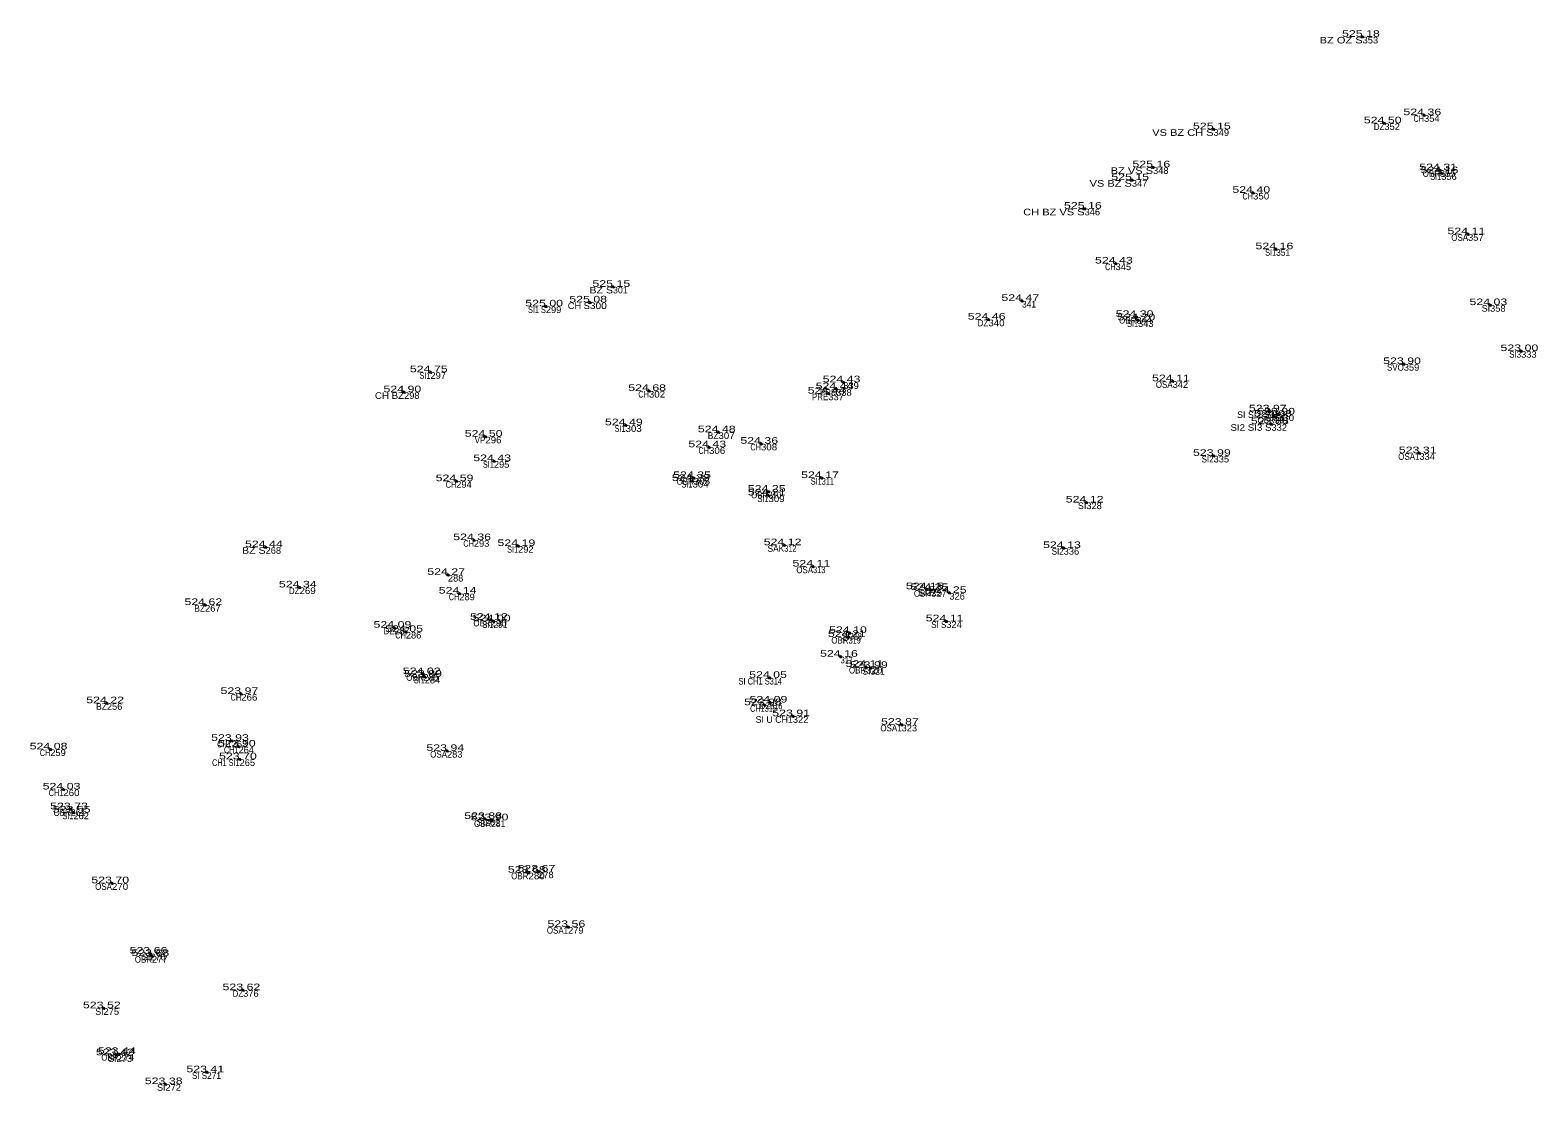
# Model space of a CAD drawing. Extents: x -643086 to -639283, y -1131805 to -1123269.
# Drawn here: x -641196.8 to -641128.3, y -1126069.6 to -1126021.4 of the extents above; entities that cross this region are included whole.
import ezdxf
from ezdxf.enums import TextEntityAlignment as Align

# ---------------------------------------------------------------- set-up
doc = ezdxf.new("R2010")
doc.units = 0
doc.header["$LTSCALE"] = 0.12
doc.header["$PDMODE"] = 32
doc.header["$PDSIZE"] = 0.06
for name, color, linetype in [('1', 7, 'Continuous'), ('2', 7, 'Continuous'), ('3', 7, 'Continuous'), ('4', 7, 'Continuous')]:
    doc.layers.add(name, color=color, linetype=linetype)

msp = doc.modelspace()

# ---------------------------------------------------------------- linework, layer by layer
at = {"layer": '1'}
for p in [(-641136.29, -1126021.73), (-641135.3, -1126025.66), (-641133.5, -1126025.29), (-641143.06, -1126025.93), (-641145.81, -1126027.66), (-641132.78, -1126027.79), (-641132.72, -1126027.93), (-641146.77, -1126028.24), (-641141.27, -1126028.82), (-641148.92, -1126029.54), (-641131.5, -1126030.7), (-641140.22, -1126031.38), (-641147.51, -1126032.03), (-641170.34, -1126033.09), (-641173.39, -1126033.98), (-641171.39, -1126033.8), (-641151.76, -1126033.73), (-641130.5, -1126033.92), (-641153.29, -1126034.58), (-641146.57, -1126034.46), (-641146.49, -1126034.61), (-641129.09, -1126036.01), (-641134.42, -1126036.6), (-641178.63, -1126036.97), (-641159.88, -1126037.43), (-641144.92, -1126037.38), (-641179.83, -1126037.88), (-641168.71, -1126037.82), (-641160.56, -1126037.94), (-641160.2, -1126037.74), (-641140.52, -1126038.75), (-641140.14, -1126038.89), (-641169.77, -1126039.38), (-641140.43, -1126039.33), (-641140.28, -1126038.99), (-641176.14, -1126039.9), (-641165.55, -1126039.7), (-641163.62, -1126040.22), (-641165.98, -1126040.38), (-641143.06, -1126040.77), (-641133.71, -1126040.65), (-641175.75, -1126041.01), (-641177.46, -1126041.92), (-641166.73, -1126041.91), (-641166.67, -1126041.78), (-641160.86, -1126041.78), (-641163.28, -1126042.4), (-641163.28, -1126042.57), (-641148.84, -1126042.89), (-641186.12, -1126044.92), (-641176.66, -1126044.6), (-641174.65, -1126044.87), (-641162.56, -1126044.83), (-641149.87, -1126044.96), (-641177.84, -1126046.18), (-641161.25, -1126045.8), (-641184.58, -1126046.75), (-641177.32, -1126047.03), (-641156.1, -1126046.83), (-641155.89, -1126046.87), (-641155.06, -1126047), (-641188.87, -1126047.55), (-641175.9, -1126048.22), (-641175.77, -1126048.29), (-641155.2, -1126048.29), (-641180.28, -1126048.58), (-641179.75, -1126048.77), (-641159.64, -1126049), (-641159.59, -1126048.82), (-641160, -1126049.9), (-641158.84, -1126050.36), (-641158.64, -1126050.41), (-641178.95, -1126050.69), (-641178.89, -1126050.81), (-641163.22, -1126050.86), (-641187.23, -1126051.59), (-641193.33, -1126052.01), (-641163.45, -1126052.1), (-641163.2, -1126051.98), (-641162.17, -1126052.6), (-641157.23, -1126052.99), (-641187.66, -1126053.72), (-641187.35, -1126053.98), (-641195.9, -1126054.11), (-641187.3, -1126054.56), (-641177.88, -1126054.18), (-641195.31, -1126055.93), (-641194.97, -1126056.83), (-641194.85, -1126056.98), (-641176.16, -1126057.27), (-641175.87, -1126057.33), (-641174.18, -1126059.71), (-641173.74, -1126059.66), (-641193.1, -1126060.19), (-641172.38, -1126062.18), (-641191.36, -1126063.39), (-641191.28, -1126063.5), (-641187.14, -1126065.05), (-641193.48, -1126065.87), (-641192.89, -1126068.01), (-641192.8, -1126067.95), (-641188.78, -1126068.78), (-641190.67, -1126069.32)]:
    msp.add_point(p, dxfattribs=at)

# ---------------------------------------------------------------- texts
at = {"layer": '2'}
for s, width, p in [('353', 1.05, (-641136.29, -1126022.03)), ('352', 1.05, (-641135.3, -1126025.96)), ('354', 1.05, (-641133.5, -1126025.59)), ('349', 1.05, (-641143.06, -1126026.23)), ('348', 1.05, (-641145.81, -1126027.96)), ('355', 1.05, (-641132.78, -1126028.09)), ('356', 1.05, (-641132.72, -1126028.23)), ('347', 1.05, (-641146.77, -1126028.54)), ('350', 1.1, (-641141.27, -1126029.12)), ('346', 1.05, (-641148.92, -1126029.84)), ('357', 1.05, (-641131.5, -1126031)), ('345', 1.05, (-641147.51, -1126032.33)), ('351', 0.95, (-641140.22, -1126031.68)), ('299', 1.05, (-641173.39, -1126034.28)), ('300', 1.15, (-641171.39, -1126034.1)), ('341', 0.95, (-641151.76, -1126034.03)), ('358', 1.05, (-641130.5, -1126034.22)), ('340', 1.1, (-641153.29, -1126034.88)), ('344', 1.05, (-641146.57, -1126034.76)), ('343', 1.05, (-641146.49, -1126034.91)), ('333', 1.05, (-641129.09, -1126036.31)), ('359', 1.05, (-641134.42, -1126036.9)), ('297', 1.05, (-641178.63, -1126037.27)), ('339', 1.05, (-641159.88, -1126037.73)), ('342', 1.05, (-641144.92, -1126037.68)), ('298', 1.05, (-641179.83, -1126038.18)), ('302', 1.1, (-641168.71, -1126038.12)), ('337', 1.05, (-641160.56, -1126038.24)), ('338', 1.05, (-641160.2, -1126038.04)), ('329', 1.05, (-641140.52, -1126039.05)), ('330', 1.1, (-641140.14, -1126039.19)), ('303', 1.1, (-641169.77, -1126039.68)), ('332', 1.05, (-641140.43, -1126039.63)), ('331', 0.95, (-641140.28, -1126039.29)), ('296', 1.1, (-641176.14, -1126040.2)), ('307', 1.1, (-641165.55, -1126040)), ('308', 1.1, (-641163.62, -1126040.52)), ('306', 1.1, (-641165.98, -1126040.68)), ('335', 1.05, (-641143.06, -1126041.07)), ('334', 1.05, (-641133.71, -1126040.95)), ('295', 1.05, (-641175.75, -1126041.31)), ('294', 1.05, (-641177.46, -1126042.22)), ('304', 1.1, (-641166.73, -1126042.21)), ('305', 1.1, (-641166.67, -1126042.08)), ('311', 0.7, (-641160.86, -1126042.08)), ('310', 0.85, (-641163.28, -1126042.7)), ('309', 1.1, (-641163.28, -1126042.87)), ('328', 1.05, (-641148.84, -1126043.19)), ('268', 1.05, (-641186.12, -1126045.22)), ('293', 1.05, (-641176.66, -1126044.9)), ('292', 1.05, (-641174.65, -1126045.17)), ('312', 0.8, (-641162.56, -1126045.13)), ('336', 1.05, (-641149.87, -1126045.26)), ('288', 1.05, (-641177.84, -1126046.48)), ('313', 0.8, (-641161.25, -1126046.1)), ('269', 1.1, (-641184.58, -1126047.05)), ('289', 1.05, (-641177.32, -1126047.33)), ('325', 1.05, (-641156.1, -1126047.13)), ('327', 1.05, (-641155.89, -1126047.17)), ('326', 1.05, (-641155.06, -1126047.3)), ('267', 1.05, (-641188.87, -1126047.85)), ('290', 1.1, (-641175.9, -1126048.52)), ('291', 0.95, (-641175.77, -1126048.59)), ('324', 1.05, (-641155.2, -1126048.59)), ('287', 1.05, (-641180.28, -1126048.88)), ('286', 1.05, (-641179.75, -1126049.07)), ('319', 0.8, (-641159.64, -1126049.3)), ('318', 0.8, (-641159.59, -1126049.12)), ('317', 0.8, (-641160, -1126050.2)), ('320', 1.1, (-641158.84, -1126050.66)), ('321', 0.95, (-641158.64, -1126050.71)), ('285', 1.05, (-641178.95, -1126050.99)), ('284', 1.05, (-641178.89, -1126051.11)), ('314', 0.8, (-641163.22, -1126051.16)), ('266', 1.1, (-641187.23, -1126051.89)), ('256', 1.05, (-641193.33, -1126052.31)), ('315', 0.8, (-641163.45, -1126052.4)), ('316', 0.8, (-641163.2, -1126052.28)), ('322', 1.05, (-641162.17, -1126052.9)), ('323', 1.05, (-641157.23, -1126053.29)), ('263', 1.05, (-641187.66, -1126054.02)), ('259', 1.05, (-641195.9, -1126054.41)), ('264', 1.05, (-641187.35, -1126054.28)), ('265', 1.05, (-641187.3, -1126054.86)), ('283', 1.05, (-641177.88, -1126054.48)), ('260', 1.1, (-641195.31, -1126056.23)), ('262', 1.05, (-641194.85, -1126057.28)), ('282', 1.05, (-641176.16, -1126057.57)), ('281', 0.95, (-641175.87, -1126057.63)), ('280', 1.1, (-641174.18, -1126060.01)), ('278', 1.05, (-641173.74, -1126059.96)), ('270', 1.1, (-641193.1, -1126060.49)), ('279', 1.05, (-641172.38, -1126062.48)), ('276', 1.05, (-641191.36, -1126063.69)), ('277', 1.05, (-641191.28, -1126063.8)), ('376', 1.05, (-641187.14, -1126065.35)), ('275', 1.05, (-641193.48, -1126066.17)), ('273', 1.05, (-641192.89, -1126068.31)), ('274', 1.05, (-641192.8, -1126068.25)), ('271', 0.95, (-641188.78, -1126069.08)), ('272', 1.05, (-641190.67, -1126069.62))]:
    msp.add_text(s, height=0.3, dxfattribs=dict(at, width=width)).set_placement(p)
for s, p in [('301', (-641170.34, -1126033.39)), ('261', (-641194.97, -1126057.13))]:
    msp.add_text(s, height=0.3, dxfattribs=at).set_placement(p)
at = {"layer": '3', "width": 1.4}
for s, p in [('525 18 ', (-641136.29, -1126021.73)), ('524 36 ', (-641133.5, -1126025.29)), ('525 15 ', (-641143.06, -1126025.93)), ('524 50 ', (-641135.3, -1126025.66)), ('525 15 ', (-641146.77, -1126028.24)), ('525 16 ', (-641145.81, -1126027.66)), ('524 31 ', (-641132.78, -1126027.79)), ('524 16 ', (-641132.72, -1126027.93)), ('524 40 ', (-641141.27, -1126028.82)), ('525 16 ', (-641148.92, -1126029.54)), ('524 11 ', (-641131.5, -1126030.7)), ('524 16 ', (-641140.22, -1126031.38)), ('524 43 ', (-641147.51, -1126032.03)), ('525 15 ', (-641170.34, -1126033.09)), ('525 00 ', (-641173.39, -1126033.98)), ('525 08 ', (-641171.39, -1126033.8)), ('524 47 ', (-641151.76, -1126033.73)), ('524 03 ', (-641130.5, -1126033.92)), ('524 46 ', (-641153.29, -1126034.58)), ('524 30 ', (-641146.57, -1126034.46)), ('524 20 ', (-641146.49, -1126034.61)), ('523 00 ', (-641129.09, -1126036.01)), ('524 75 ', (-641178.63, -1126036.97)), ('523 90 ', (-641134.42, -1126036.6)), ('524 68 ', (-641168.71, -1126037.82)), ('524 44 ', (-641160.2, -1126037.74)), ('524 43 ', (-641159.88, -1126037.43)), ('524 11 ', (-641144.92, -1126037.38)), ('524 90 ', (-641179.83, -1126037.88)), ('524 44 ', (-641160.56, -1126037.94)), ('523 97 ', (-641140.52, -1126038.75)), ('524 08 ', (-641140.28, -1126038.99)), ('523 90 ', (-641140.14, -1126038.89)), ('524 49 ', (-641169.77, -1126039.38)), ('524 48 ', (-641165.55, -1126039.7)), ('523 86 ', (-641140.43, -1126039.33)), ('524 50 ', (-641176.14, -1126039.9)), ('524 43 ', (-641165.98, -1126040.38)), ('524 36 ', (-641163.62, -1126040.22)), ('524 43 ', (-641175.75, -1126041.01)), ('523 99 ', (-641143.06, -1126040.77)), ('523 31 ', (-641133.71, -1126040.65)), ('524 59 ', (-641177.46, -1126041.92)), ('524 28 ', (-641166.73, -1126041.91)), ('524 35 ', (-641166.67, -1126041.78)), ('524 17 ', (-641160.86, -1126041.78)), ('524 25 ', (-641163.28, -1126042.4)), ('524 21 ', (-641163.28, -1126042.57)), ('524 12 ', (-641148.84, -1126042.89)), ('524 36 ', (-641176.66, -1126044.6)), ('524 44 ', (-641186.12, -1126044.92)), ('524 19 ', (-641174.65, -1126044.87)), ('524 12 ', (-641162.56, -1126044.83)), ('524 13 ', (-641149.87, -1126044.96)), ('524 11 ', (-641161.25, -1126045.8)), ('524 27 ', (-641177.84, -1126046.18)), ('524 34 ', (-641184.58, -1126046.75)), ('524 14 ', (-641177.32, -1126047.03)), ('524 15 ', (-641156.1, -1126046.83)), ('524 25 ', (-641155.89, -1126046.87)), ('524 25 ', (-641155.06, -1126047)), ('524 62 ', (-641188.87, -1126047.55)), ('524 09 ', (-641180.28, -1126048.58)), ('524 05 ', (-641179.75, -1126048.77)), ('524 12 ', (-641175.9, -1126048.22)), ('524 00 ', (-641175.77, -1126048.29)), ('524 11 ', (-641155.2, -1126048.29)), ('524 21 ', (-641159.64, -1126049)), ('524 10 ', (-641159.59, -1126048.82)), ('524 16 ', (-641160, -1126049.9)), ('524 02 ', (-641178.95, -1126050.69)), ('523 89 ', (-641178.89, -1126050.81)), ('524 11 ', (-641158.84, -1126050.36)), ('523 99 ', (-641158.64, -1126050.41)), ('524 05 ', (-641163.22, -1126050.86)), ('524 22 ', (-641193.33, -1126052.01)), ('523 97 ', (-641187.23, -1126051.59)), ('523 98 ', (-641163.45, -1126052.1)), ('524 09 ', (-641163.2, -1126051.98)), ('523 91 ', (-641162.17, -1126052.6)), ('523 87 ', (-641157.23, -1126052.99)), ('524 08 ', (-641195.9, -1126054.11)), ('523 93 ', (-641187.66, -1126053.72)), ('523 90 ', (-641187.35, -1126053.98)), ('523 94 ', (-641177.88, -1126054.18)), ('523 70 ', (-641187.3, -1126054.56)), ('524 03 ', (-641195.31, -1126055.93)), ('523 73 ', (-641194.97, -1126056.83)), ('523 55 ', (-641194.85, -1126056.98)), ('523 88 ', (-641176.16, -1126057.27)), ('523 90 ', (-641175.87, -1126057.33)), ('523 68 ', (-641174.18, -1126059.71)), ('523 67 ', (-641173.74, -1126059.66)), ('523 70 ', (-641193.1, -1126060.19)), ('523 56 ', (-641172.38, -1126062.18)), ('523 66 ', (-641191.36, -1126063.39)), ('523 68 ', (-641191.28, -1126063.5)), ('523 62 ', (-641187.14, -1126065.05)), ('523 52 ', (-641193.48, -1126065.87)), ('523 44 ', (-641192.8, -1126067.95)), ('523 42 ', (-641192.89, -1126068.01)), ('523 38 ', (-641190.67, -1126069.32)), ('523 41 ', (-641188.78, -1126068.78))]:
    msp.add_text(s, height=0.3, dxfattribs=at).set_placement(p, align=Align.CENTER)
at = {"layer": '4'}
for s, width, p in [('BZ OZ S', 1.25, (-641136.29, -1126022.03)), ('DZ', 0.9, (-641135.3, -1126025.96)), ('CH', 0.8, (-641133.5, -1126025.59)), ('VS BZ CH S', 1.25, (-641143.06, -1126026.23)), ('BZ VS S', 1.25, (-641145.81, -1126027.96)), ('OBR', 0.9, (-641132.78, -1126028.09)), ('SI1', 0.8, (-641132.72, -1126028.23)), ('VS BZ S', 1.25, (-641146.77, -1126028.54)), ('CH', 0.8, (-641141.27, -1126029.12)), ('CH BZ VS S', 1.25, (-641148.92, -1126029.84)), ('OSA', 0.9, (-641131.5, -1126031)), ('CH', 0.8, (-641147.51, -1126032.33)), ('SI1', 0.8, (-641140.22, -1126031.68)), ('BZ S', 1.2, (-641170.34, -1126033.39)), ('SI1 S', 0.8, (-641173.39, -1126034.28)), ('CH S', 1.05, (-641171.39, -1126034.1)), ('DZ', 0.9, (-641153.29, -1126034.88)), ('OBR', 0.9, (-641146.57, -1126034.76)), ('SI1', 0.8, (-641146.49, -1126034.91)), ('SI3', 0.9, (-641129.09, -1126036.31)), ('SVO', 0.9, (-641134.42, -1126036.9)), ('SI1', 0.8, (-641178.63, -1126037.27)), ('OSA', 0.9, (-641144.92, -1126037.68)), ('CH BZ', 1.1, (-641179.83, -1126038.18)), ('CH', 0.8, (-641168.71, -1126038.12)), ('PRE', 0.9, (-641160.56, -1126038.24)), ('PRE', 0.9, (-641160.2, -1126038.04)), ('SI2', 0.9, (-641140.14, -1126039.19)), ('SI1', 0.8, (-641169.77, -1126039.68)), ('SI2 SI3 S', 1.1, (-641140.43, -1126039.63)), ('OBR', 0.9, (-641140.28, -1126039.29)), ('VP', 0.9, (-641176.14, -1126040.2)), ('BZ', 0.95, (-641165.55, -1126040)), ('CH', 0.8, (-641163.62, -1126040.52)), ('CH', 0.8, (-641165.98, -1126040.68)), ('SI2', 0.9, (-641143.06, -1126041.07)), ('OSA1', 0.9, (-641133.71, -1126040.95)), ('SI1', 0.8, (-641175.75, -1126041.31)), ('CH', 0.8, (-641177.46, -1126042.22)), ('OBR', 0.9, (-641166.67, -1126042.08)), ('SI1', 0.8, (-641166.73, -1126042.21)), ('SI1', 0.8, (-641160.86, -1126042.08)), ('OBR', 0.9, (-641163.28, -1126042.7)), ('SI1', 0.8, (-641163.28, -1126042.87)), ('BZ S', 1.2, (-641186.12, -1126045.22)), ('CH', 0.8, (-641176.66, -1126044.9)), ('SI1', 0.8, (-641174.65, -1126045.17)), ('SAK', 0.95, (-641162.56, -1126045.13)), ('SI2', 0.9, (-641149.87, -1126045.26)), ('OSA', 0.9, (-641161.25, -1126046.1)), ('DZ', 0.9, (-641184.58, -1126047.05)), ('CH', 0.8, (-641177.32, -1126047.33)), ('OBR', 0.9, (-641155.89, -1126047.17)), ('BZ', 0.95, (-641188.87, -1126047.85)), ('OBR', 0.9, (-641175.9, -1126048.52)), ('SI1', 0.8, (-641175.77, -1126048.59)), ('SI S', 0.9, (-641155.2, -1126048.59)), ('DZ', 0.9, (-641180.28, -1126048.88)), ('CH', 0.8, (-641179.75, -1126049.07)), ('OBR', 0.9, (-641159.64, -1126049.3)), ('OBR', 0.9, (-641158.84, -1126050.66)), ('OBR', 0.9, (-641178.95, -1126050.99)), ('SI1', 0.8, (-641178.89, -1126051.11)), ('SI CH1 S', 0.85, (-641163.22, -1126051.16)), ('CH', 0.8, (-641187.23, -1126051.89)), ('BZ', 0.95, (-641193.33, -1126052.31)), ('CH1', 0.8, (-641163.45, -1126052.4)), ('DZ', 0.9, (-641163.2, -1126052.28)), ('OSA1', 0.9, (-641157.23, -1126053.29)), ('CH1', 0.8, (-641187.66, -1126054.02)), ('CH', 0.8, (-641195.9, -1126054.41)), ('CH1 SI1', 0.8, (-641187.3, -1126054.86)), ('CH1', 0.8, (-641187.35, -1126054.28)), ('OSA', 0.9, (-641177.88, -1126054.48)), ('CH1', 0.8, (-641195.31, -1126056.23)), ('OBR', 0.9, (-641194.97, -1126057.13)), ('SI1', 0.8, (-641194.85, -1126057.28)), ('OBR', 0.9, (-641175.87, -1126057.63)), ('OBR', 0.9, (-641174.18, -1126060.01)), ('OSA', 0.9, (-641193.1, -1126060.49)), ('OSA1', 0.9, (-641172.38, -1126062.48)), ('OBR', 0.9, (-641191.28, -1126063.8)), ('DZ', 0.9, (-641187.14, -1126065.35)), ('OBR', 0.9, (-641192.8, -1126068.25)), ('SI S', 0.9, (-641188.78, -1126069.08))]:
    msp.add_text(s, height=0.3, dxfattribs=dict(at, width=width)).set_placement(p, align=Align.RIGHT)
for s, p in [('SI', (-641130.5, -1126034.22)), ('SI SI2 S', (-641140.52, -1126039.05)), ('SI', (-641148.84, -1126043.19)), ('SI', (-641156.1, -1126047.13)), ('SI', (-641159.59, -1126049.12)), ('SI', (-641158.64, -1126050.71)), ('SI U CH1', (-641162.17, -1126052.9)), ('SI', (-641176.16, -1126057.57)), ('SI', (-641191.36, -1126063.69)), ('SI', (-641193.48, -1126066.17)), ('SI', (-641192.89, -1126068.31)), ('SI', (-641190.67, -1126069.62))]:
    msp.add_text(s, height=0.3, dxfattribs=at).set_placement(p, align=Align.RIGHT)

doc.saveas('drawing.dxf')
